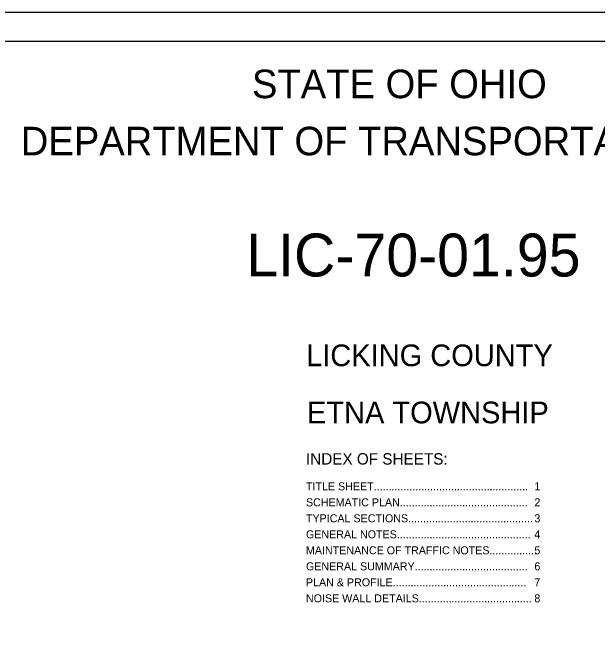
# Model space of a CAD drawing. Extents: x 0 to 34, y 0 to 22.
# Drawn here: x 9.77 to 20.02, y 11.1 to 22 of the extents above; entities that cross this region are included whole.
import ezdxf

# ---------------------------------------------------------------- set-up
doc = ezdxf.new("R2010")
doc.units = 0
for name, color, linetype in [('SH_Border', 7, 'Continuous'), ('SH_Cut_Line', 7, 'Continuous'), ('SH_Text', 7, 'Continuous')]:
    doc.layers.add(name, color=color, linetype=linetype)

msp = doc.modelspace()

# ---------------------------------------------------------------- linework, layer by layer
at = {"layer": 'SH_Border'}
msp.add_lwpolyline([(1.5, 21.5), (33.5, 21.5), (33.5, 0.5), (1.5, 0.5)], close=True, dxfattribs=at)
at = {"layer": 'SH_Cut_Line'}
msp.add_lwpolyline([(0, 0), (34, 0), (34, 22), (0, 22)], close=True, dxfattribs=at)

# ---------------------------------------------------------------- texts
at = {"layer": 'SH_Text'}
for s, height, p in [('STATE OF OHIO', 0.5, (13.968, 20.5)), ('DEPARTMENT OF TRANSPORTATION', 0.5, (9.92, 19.5)), ('LIC-70-01.95', 0.75, (13.868, 17.38)), ('LICKING COUNTY', 0.38, (14.917, 15.81)), ('ETNA TOWNSHIP', 0.38, (14.932, 14.81)), ('INDEX OF SHEETS:', 0.2, (14.914, 14.088)), ('TITLE SHEET....................................................', 0.14, (14.914, 13.638)), ('1', 0.14, (18.914, 13.638)), ('SCHEMATIC PLAN...........................................', 0.14, (14.914, 13.358)), ('2', 0.14, (18.914, 13.358)), ('TYPICAL SECTIONS..........................................', 0.14, (14.914, 13.078)), ('3', 0.14, (18.914, 13.078)), ('GENERAL NOTES.............................................', 0.14, (14.914, 12.798)), ('4', 0.14, (18.914, 12.798)), ('MAINTENANCE OF TRAFFIC NOTES................', 0.14, (14.914, 12.518)), ('5', 0.14, (18.914, 12.518)), ('GENERAL SUMMARY......................................', 0.14, (14.914, 12.238)), ('6', 0.14, (18.914, 12.238)), ('PLAN & PROFILE.............................................', 0.14, (14.914, 11.958)), ('7', 0.14, (18.914, 11.958)), ('NOISE WALL DETAILS......................................', 0.14, (14.914, 11.678)), ('8', 0.14, (18.914, 11.678))]:
    msp.add_text(s, height=height, dxfattribs=at).set_placement(p)

doc.saveas('drawing.dxf')
